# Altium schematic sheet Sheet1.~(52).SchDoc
size A
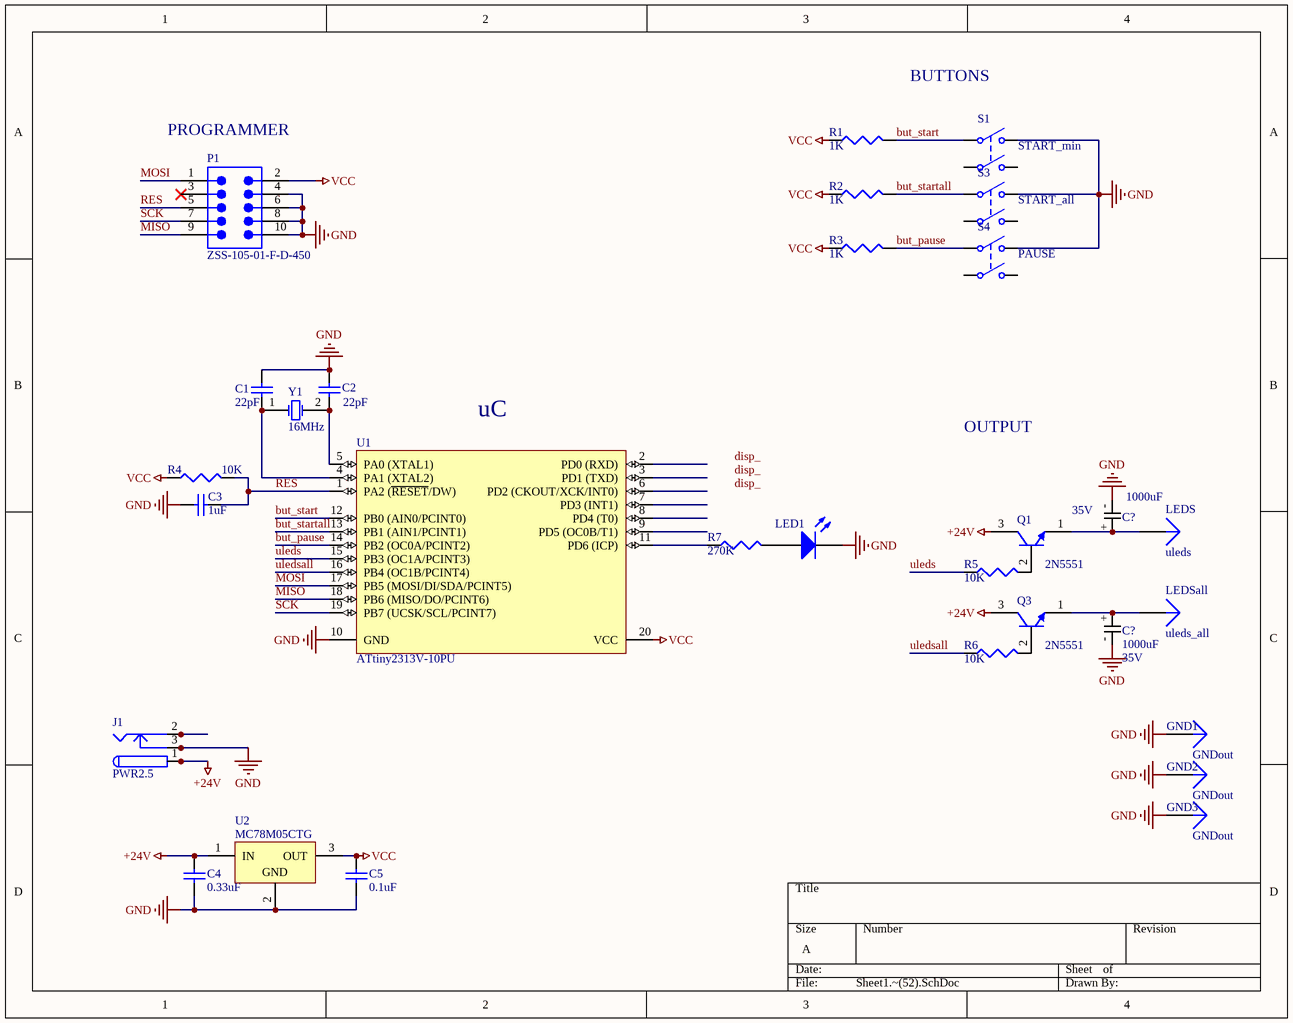
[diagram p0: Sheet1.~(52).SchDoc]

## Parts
(Parts that share a designator on the sheet are numbered #1, #2 ... from top to bottom, then left to right.)
C1  value 22pF  [CAPC1608L]  (hidden comment: Cap Semi)
C2  value 22pF  [CAPC1608L]  (hidden comment: Cap Semi)
C3  value 1uF  [CAPC1608L]  (hidden comment: Cap Semi)
C4  value 0.33uF  [CAPC1608L]  (hidden comment: Cap Semi)
C5  value 0.1uF  [CAPC1608L]  (hidden comment: Cap Semi)
C?#1  Capasitance: 1000uF  Voltage: 35V  (hidden comment: Cap1000uF30V)
C?#2  Capasitance: 1000uF  Voltage: 35V  (hidden comment: Cap1000uF30V)
GND1  GNDout  [PIN1]
GND2  GNDout  [PIN1]
GND3  GNDout  [PIN1]
J1  PWR2.5  [PCBComponent_1]
LED1  151051YS04000  [Type 5mm]  (value not drawn)
LEDS  uleds  [PIN1]
LEDSall  uleds_all  [PIN1]
P1  ZSS-105-01-F-D-450  [SMTC-ZSS-105-01-X-D-450]
Q1  2N5551  [ONSC-TO-92-3-29-11_AM_BL]
Q3  2N5551  [ONSC-TO-92-3-29-11_AM_BL]
R1  value 1K  [CAPC1608L]  (hidden comment: Res3)
R2  value 1K  [CAPC1608L]  (hidden comment: Res3)
R3  value 1K  [CAPC1608L]  (hidden comment: Res3)
R4  value 10K  [CAPC1608L]  (hidden comment: Res3)
R5  value 10K  [CAPC1608L]  (hidden comment: Res3)
R6  value 10K  [CAPC1608L]  (hidden comment: Res3)
R7  value 270K  [CAPC1608L]  (hidden comment: Res3)
S1  START_min  [key]
S3  START_all  [key]
S4  PAUSE  [key]
U1  ATtiny2313V-10PU  [20P3]
U2  MC78M05CTG  [TO220]
Y1  16MHz  [PCBComponent_1 - duplicate]

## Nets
+24V: C4.2 J1.1 J1.1A J1.1B Q1.3(C) Q3.3(C) U2.1(IN)
GND: C1.1 C2.1 C3.2 C4.1 C5.1 C?#1.- C?#2.- GND1.1 GND2.1 GND3.1 J1.3 J1.3A J1.3B LED1.1(K) P1.4 P1.6 P1.8 P1.10 S1.2(NO1) S3.2(NO1) S4.2(NO1) U1.10(GND) U2.2(GND)
VCC: C5.2 P1.2 R1.1 R2.1 R3.1 R4.1 U1.20(VCC) U2.3(OUT)
but_pause: R3.2 S4.1(COMMON1) U1.14(PB2_(OC0A/PCINT2))
but_start: R1.2 S1.1(COMMON1) U1.12(PB0_(AIN0/PCINT0))
but_startall: R2.2 S3.1(COMMON1) U1.13(PB1_(AIN1/PCINT1))
MISO: P1.9 U1.18(PB6_(MISO/DO/PCINT6))
MOSI: P1.1 U1.17(PB5_(MOSI/DI/SDA/PCINT5))
RES: C3.1 P1.5 R4.2 U1.1(PA2_(~{RESET}/DW))
SCK: P1.7 U1.19(PB7_(UCSK/SCL/PCINT7))
uleds: R5.1 U1.15(PB3_(OC1A/PCINT3))
uledsall: R6.1 U1.16(PB4_(OC1B/PCINT4))
NetC1_2: C1.2 U1.4(PA1_(XTAL2)) Y1.1(OSC1)
NetC2_2: C2.2 U1.5(PA0_(XTAL1)) Y1.2(OSC2)
NetC?#1_+: C?#1.+ LEDS.1 Q1.1(E)
NetC?#2_+: C?#2.+ LEDSall.1 Q3.1(E)
NetJ1_2: J1.2 J1.2A J1.2B
NetLED1_2: LED1.2(A) R7.2
NetQ1_2: Q1.2(B) R5.2
NetQ3_2: Q3.2(B) R6.2
NetR7_1: R7.1 U1.11(PD6_(ICP))

Not connected (* = marked no-connect by the designer): P1 3*; S1 3(COMMON2) 4(NO2); S3 3(COMMON2) 4(NO2); S4 3(COMMON2) 4(NO2); U1 2(PD0_(RXD)) 3(PD1_(TXD)) 6(PD2_(CKOUT/XCK/INT0)) 7(PD3_(INT1)) 8(PD4_(T0)) 9(PD5_(OC0B/T1))

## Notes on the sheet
- BUTTONS
- (near P1) PROGRAMMER
- (near U1) uC
- OUTPUT
- Labels drawn without touching a wire or pin: disp_

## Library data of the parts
C1-C5 = Cap Semi: Capacitor (Semiconductor SIM Model)
GND1-GND3 LEDS LEDSall = Plug
J1 = PWR2.5: Low Voltage Power Supply Connector
LED1 = CMP-1488-00010-1: THT LED round mono-color color lens, WL-TMRW, Yellow; Manufacturer: Wuerth Elektronik
P1 = CMP-1024-00461-1: Manufacturer: Samtec; Pitch: 2.54 mm
Q1 Q3 = CMP-1048-01479-1: Amplifier Transistor, NPN Silicon, 3-Pin TO-92, Pb-Free, Tape and Reel; PartNumber: 2N5551RL1G; Manufacturer: On Semiconductor; fT Min (MHz): 100; IC Continuous (A): 0.6
R1-R7 = Res3: Resistor
S1 S3 S4 = SW-DPST: Double-Pole, Single-Throw Switch
U1 = CMP-0093-00017-1: Low Power tinyAVR® 8-Bit Microcontroller, 2K Flash Memory, 10MHz, Industrial Temperature, 20-Lead PDIP, Pb-Free
U2 = CMP-0244-00483-1: Positive Voltage Regulator, 5V, 3-Pin TO-220
Y1 = XTAL: Crystal Oscillator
